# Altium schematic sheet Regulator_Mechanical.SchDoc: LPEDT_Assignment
size A; DocumentNumber: 1; Revision: 1; SheetNumber: 2; SheetTotal: 2
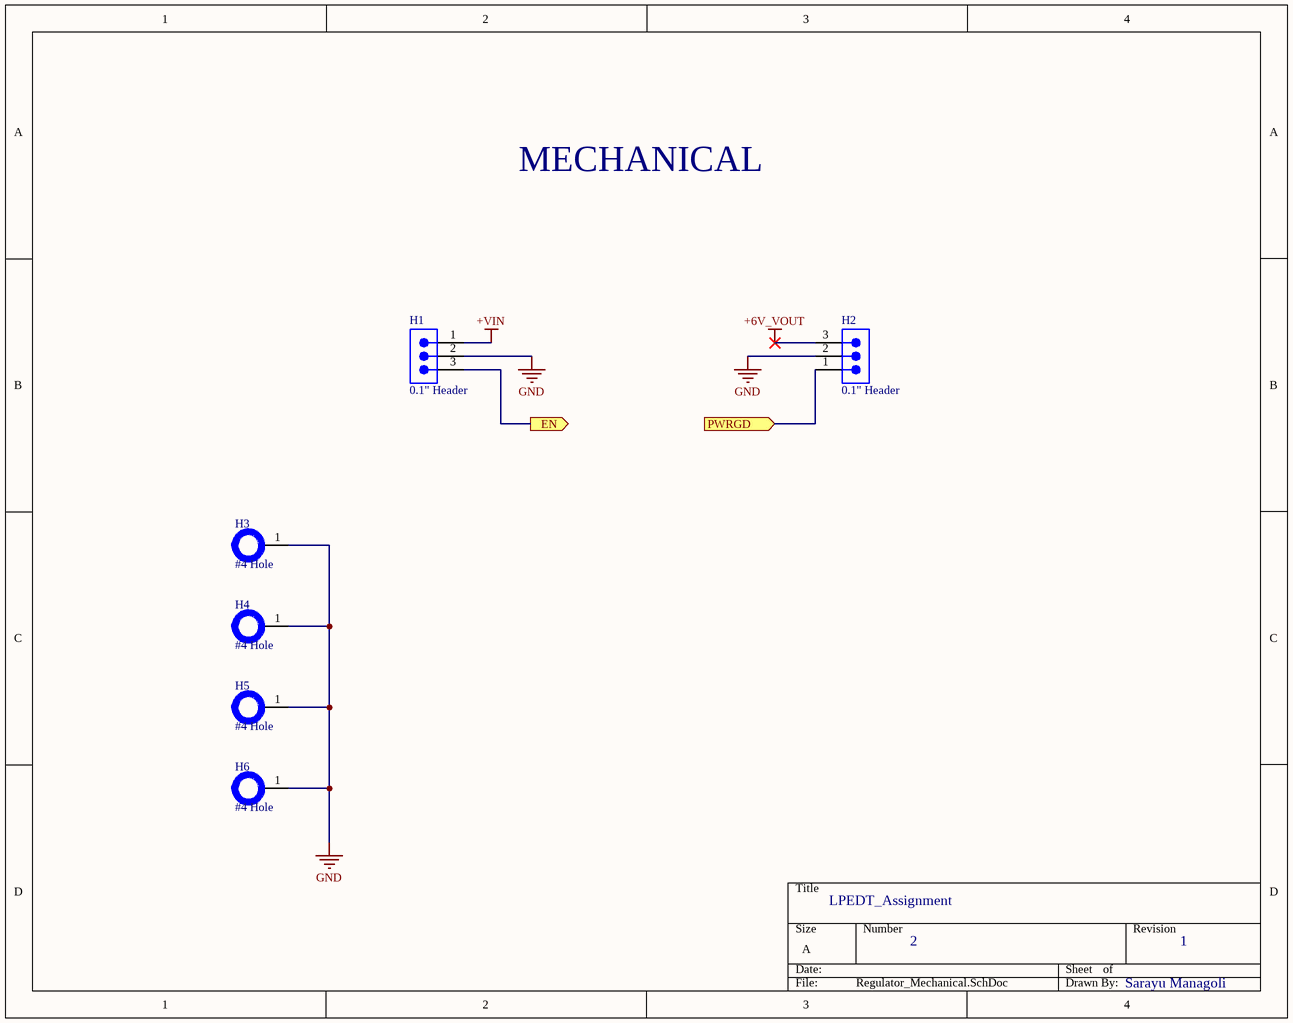
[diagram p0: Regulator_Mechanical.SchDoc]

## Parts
H1  0.1" Header  [3-PIN_MALE_HEADER_01-IN]
H2  0.1" Header  [3-PIN_MALE_HEADER_01-IN]
H3  #4 Hole  [HOLE_#4]  (no BOM)
H4  #4 Hole  [HOLE_#4]  (no BOM)
H5  #4 Hole  [HOLE_#4]  (no BOM)
H6  #4 Hole  [HOLE_#4]  (no BOM)

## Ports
EN (out), PWRGD (in)

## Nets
+6V_VOUT: H2.3
+VIN: H1.1
GND: H1.2 H2.2 H3.1 H4.1 H5.1 H6.1
EN: H1.3 ; port EN
PWRGD: H2.1 ; port PWRGD

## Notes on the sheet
- MECHANICAL
- Sarayu Managoli

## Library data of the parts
H1 H2 = PRPC003SAAN-RC: CONN HEADER VERT 3POS 2.54MM; Manufacturer: Sullins; Connector Type: Header, Unshrouded, Breakaway; Number of Positions: 3; Number of Positions Loaded: All; Pitch: 0.100" (2.54mm); Online Catalog: 0.100" (2.54mm) Pitch Connector Headers; Other Names: S9510E-03  S9510E-03-ND
H3-H6 = HOLE_#4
